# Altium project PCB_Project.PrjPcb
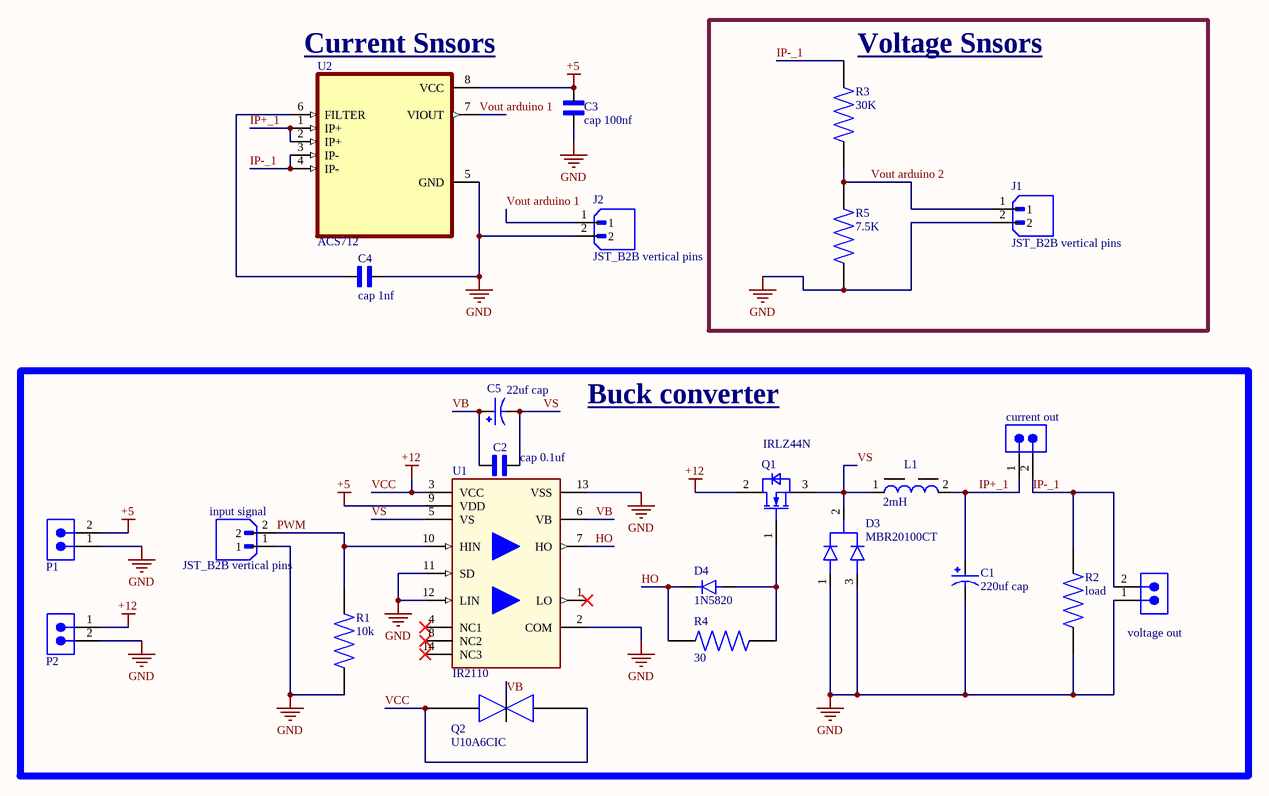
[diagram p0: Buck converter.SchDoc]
1 sheet, 24 parts. Net scope: global (net labels, ports and power ports of the same name join across sheets).
Board file: Buck converter.PcbDoc

## Sheet Buck converter.SchDoc
size 381 x 241 mm; SheetNumber: 1; SheetTotal: 1

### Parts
C1  220uf cap  [cap 22uf 50V]
C2  cap 0.1uf  [CAP ceramic]
C3  cap 100nf  [CAP ceramic]
C4  cap 1nf  [CAP ceramic]
C5  22uf cap  [cap 22uf 50V]
current_out  691305540002  [Horizontal Pluggable]  (value not drawn)
D3  MBR20100CT  [TO254P1066X482X2286-3]
D4  1N5820  [1N4007]
input_signal  JST_B2B vertical pins  [JST_B2B vertical pins]
J1  JST_B2B vertical pins  [JST_B2B vertical pins]
J2  JST_B2B vertical pins  [JST_B2B vertical pins]
L1  value 2mH  [2mH E shape]  (hidden comment: 2mH E shape)
P1  691305540002  [Horizontal Pluggable]  (value not drawn)
P2  691305540002  [Horizontal Pluggable]  (value not drawn)
Q1  IRLZ44N  [IFX-PG-TO220-3-904-1]
Q2  U10A6CIC  [TO254P1066X482X2286-3]
R1  10k  [RES]
R2  load  [RES]
R3  30K  [RES]
R4  30  [RES]
R5  7.5K  [RES]
U1  IR2110  [DIP762W46P254L1930H533Q14B]
U2  ACS712  [SOIC127P600X175-8N]
voltage_out  691305540002  [Horizontal Pluggable]  (value not drawn)

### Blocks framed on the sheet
Voltage Snsors: J1 R3 R5
Buck converter: C1 C2 C5 current_out D3 D4 input_signal L1 P1 P2 Q1 Q2 R1 R2 R4 U1 voltage_out

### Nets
+5: C3.2 P1.2 U1.9(VDD) U2.8(VCC)
GND: C1.N C3.1 C4.2 D3.1(ANODE1) D3.3(ANODE2) input_signal.1 J1.2 J2.2 P1.1 P2.2 R1.1 R2.1 R5.1 U1.2(COM) U1.11(SD) U1.12(LIN) U1.13(VSS) U2.5(GND) voltage_out.1
VCC: P2.1 Q1.2(DRAIN) Q2.1(Anode) Q2.3(Anode) U1.3(VCC)  [also labelled +12]
HO: D4.C R4.2 U1.7(HO)
IP+_1: C1.P current_out.1 L1.2 U2.1(IP+) U2.2(IP+)
IP-_1: current_out.2 R2.2 R3.2 U2.3(IP-) U2.4(IP-) voltage_out.2
PWM: input_signal.2 R1.2 U1.10(HIN)
VB: C2.1 C5.P Q2.2(Cathode) U1.6(VB)
Vout arduino 1: J2.1 U2.7(VIOUT)
Vout arduino 2: J1.1 R3.1 R5.2
VS: C2.2 C5.N D3.2(COMMON_CATHODE) L1.1 Q1.3(SOURCE) U1.5(VS)
NetC4_1: C4.1 U2.6(FILTER)
NetD4_A: D4.A Q1.1(GATE) R4.1

Not connected (* = marked no-connect by the designer): U1 1(LO)* 4(NC1)* 8(NC2)* 14(NC3)*

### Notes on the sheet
- (near U2) Current Snsors

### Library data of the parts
C1 C5 = 22uf cap: CAP ALUM 22UF 20% 400V RADIAL; MF: Panasonic; MP: EEU-ED2G220S
C2-C4 = cap 100nF: Capacitor, Ceramic, 100nF, 100VDC, 10-% Tol, 10+% Tol, X7R-TC Code, -15, 15%-TC; MF: AVX; MP: SR291C104KARTR1
current_out P1 P2 voltage_out = horizontal Pluggable: WR-TBL Series 3055 PCB Header Horizontal Entry with Plastic Latches, THT, pitch 5.08mm, 2p; Manufacturer: Wurth Elektronik; Modularity: No; Rated Current: 16A; Working Voltage: 300V
D3 = MBR20100CT: Diode Array 1 Pair Common Cathode Schottky 100 V 10A Through Hole TO-262-3 Long Leads, IÂ²Pak, TO-262AA; MF: Diodes Inc.
D4 = 1N4007: Diode, DO-41, 1000V, 1A, 175Â°C; MF: Diotec Semiconductor
input_signal J1 J2 = JST_B2B vertical pins: Connector Header Through Hole 2 position 0.098 (2.50mm); MF: JST Sales; MP: B2B-XH-A (LF)(SN)
L1 = CMP-006-00023-3
Q1 = IRLZ44N: OptiMOS 3 Power-Transistor, VDS 100V; Manufacturer: Infineon Technologies
Q2 = Diode U10A6CIC: Ultra Fast Recovery Rectifier Diode 600V 10A; MF: Vishay Siliconix; MP: IRF9640
R1-R3 R5 = RES: 1.07 kOhms Â±1% 0.25W, 1/4W Through Hole Resistor Axial - Metal Film; MF: Yageo; MP: MFR-25FBF52-1K
R4 = RES: MF: Yageo; MP: MFR-25FBF52-1K
U1 = IR2110: High and Low Side Driver; Manufacturer: Infineon Technologies
U2 = ACS712: Fully Integrated, Hall-Effect-Based Linear Current Sensor IC with 2.4 kVRMS Isolation and a Low-Resistance Current Conductor; MF: Allegro; MP: ACS712ELCTR-20A-S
